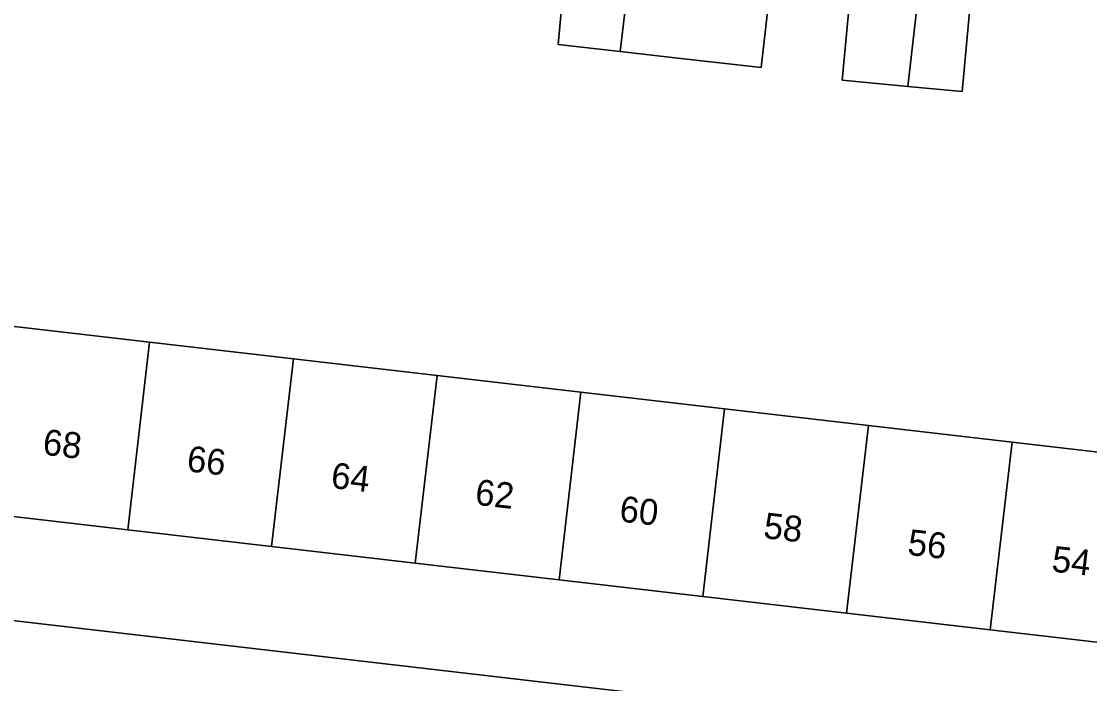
# Model space of a CAD drawing. Extents: x 162250 to 162661, y 380743 to 381606.
# Drawn here: x 162339.15 to 162380.48, y 380905.29 to 380930.93 of the extents above; entities that cross this region are included whole.
import ezdxf

# ---------------------------------------------------------------- set-up
doc = ezdxf.new("R2010")
doc.units = 0
for name, color, linetype in [('IMGEO_Erf', 7, 'Continuous'), ('IMGEO_Pand', 7, 'Continuous'), ('IMGEO_Pand_nummerreeks', 7, 'Continuous'), ('IMGEO_Voetpad_open', 7, 'Continuous')]:
    doc.layers.add(name, color=color, linetype=linetype)

msp = doc.modelspace()

# ---------------------------------------------------------------- linework, layer by layer
at = {"layer": 'IMGEO_Erf'}
for points in [[(162368.187, 380932.778), (162367.779, 380929.143), (162364.555, 380929.505), (162362.325, 380929.756), (162359.918, 380930.026), (162360.258, 380933.685)], [(162375.88, 380931.706), (162375.556, 380928.215), (162373.449, 380928.411), (162370.911, 380928.646), (162371.268, 380932.492)], [(162338.551, 380919.15), (162344.113, 380918.505), (162349.676, 380917.86), (162355.238, 380917.215), (162360.799, 380916.571), (162366.362, 380915.926), (162371.924, 380915.282), (162377.487, 380914.637), (162383.048, 380913.992)]]:
    msp.add_lwpolyline(points, dxfattribs=at)
msp.add_lwpolyline([(162359.955, 380909.304), (162354.393, 380909.948), (162348.831, 380910.593), (162343.269, 380911.238), (162337.707, 380911.883), (162332.144, 380912.528), (162326.582, 380913.172), (162321.02, 380913.817), (162315.458, 380914.462), (162309.896, 380915.106), (162304.215, 380915.765), (162303.756, 380911.805), (162387.38, 380902.085), (162387.886, 380906.066), (162382.204, 380906.725), (162376.642, 380907.369), (162371.079, 380908.014), (162365.517, 380908.659)], close=True, dxfattribs=at)
at = {"layer": 'IMGEO_Pand'}
for points in [[(162362.785, 380933.665), (162360.282, 380933.946), (162360.258, 380933.685), (162359.918, 380930.026), (162362.325, 380929.756)], [(162368.187, 380932.778), (162368.218, 380933.054), (162364.919, 380933.425), (162362.785, 380933.665), (162362.325, 380929.756), (162364.555, 380929.505), (162367.779, 380929.143)], [(162373.921, 380932.47), (162371.289, 380932.714), (162371.268, 380932.492), (162370.911, 380928.646), (162373.449, 380928.411)], [(162375.88, 380931.706), (162375.933, 380932.283), (162373.921, 380932.47), (162373.449, 380928.411), (162375.556, 380928.215)], [(162343.269, 380911.238), (162344.113, 380918.505), (162338.551, 380919.15), (162337.707, 380911.883)], [(162343.269, 380911.238), (162348.831, 380910.593), (162349.676, 380917.86), (162344.113, 380918.505)], [(162355.238, 380917.215), (162349.676, 380917.86), (162348.831, 380910.593), (162354.393, 380909.948)], [(162355.238, 380917.215), (162354.393, 380909.948), (162359.955, 380909.304), (162360.799, 380916.571)], [(162366.362, 380915.926), (162360.799, 380916.571), (162359.955, 380909.304), (162365.517, 380908.659)], [(162366.362, 380915.926), (162365.517, 380908.659), (162371.079, 380908.014), (162371.924, 380915.282)], [(162376.642, 380907.369), (162377.487, 380914.637), (162371.924, 380915.282), (162371.079, 380908.014)], [(162376.642, 380907.369), (162382.204, 380906.725), (162383.048, 380913.992), (162377.487, 380914.637)]]:
    msp.add_lwpolyline(points, close=True, dxfattribs=at)
at = {"layer": 'IMGEO_Voetpad_open'}
msp.add_lwpolyline([(162446.741, 380900.601), (162441.119, 380900.4), (162435.376, 380900.195), (162435.233, 380904.199), (162432.846, 380904.146), (162430.939, 380904.454), (162424.628, 380905.15), (162418.77, 380905.796), (162412.864, 380906.447), (162406.649, 380907.132), (162403.615, 380907.534), (162403.427, 380905.895), (162390.97, 380907.322), (162391.079, 380908.948), (162388.264, 380909.325), (162387.886, 380906.066), (162387.38, 380902.085), (162303.756, 380911.805), (162301.694, 380912.045), (162277.054, 380914.909), (162276.814, 380911.134)], dxfattribs=at)

# ---------------------------------------------------------------- texts
at = {"layer": 'IMGEO_Pand_nummerreeks'}
for s, p in [('68', (162339.944, 380914.16)), ('66', (162345.519, 380913.514)), ('64', (162351.097, 380912.868)), ('62', (162356.673, 380912.221)), ('60', (162362.257, 380911.573)), ('58', (162367.835, 380910.927)), ('56', (162373.41, 380910.281)), ('54', (162378.988, 380909.635))]:
    msp.add_text(s, height=1, rotation=353.3879, dxfattribs=at).set_placement(p)

doc.saveas('drawing.dxf')
